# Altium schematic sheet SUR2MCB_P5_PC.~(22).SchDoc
size 420 x 297 mm; Scale: 1:1; Обозначение документа: АБВГ.123456.001 Э3
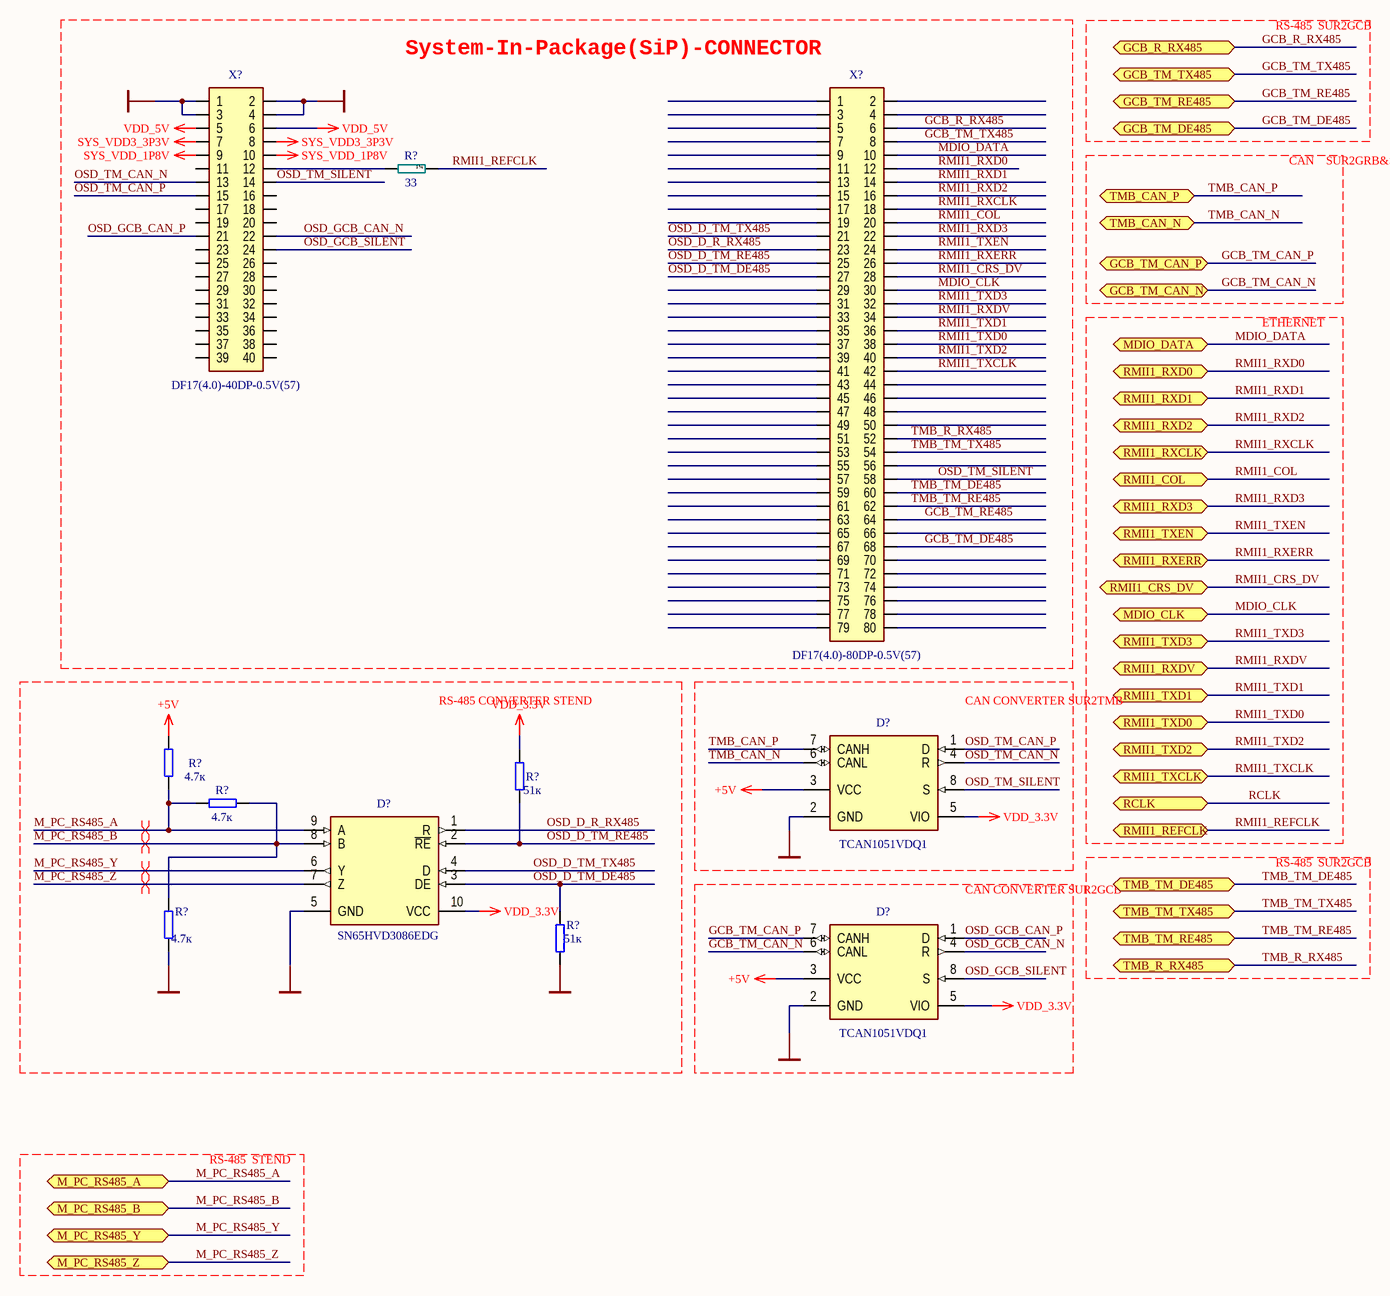
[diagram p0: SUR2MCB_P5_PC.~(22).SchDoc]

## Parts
(Parts that share a designator on the sheet are numbered #1, #2 ... from top to bottom, then left to right.)
D?#1  value TCAN1051VDQ1  [SOP-8-3.9X5-1.27]
D?#2  value SN65HVD3086EDG  [MSOP-10-3X3-0.5]
D?#3  value TCAN1051VDQ1  [SOP-8-3.9X5-1.27]
R?#1  value 33  [R0402]
R?#2  value 51к  [R0603]
R?#3  value 4.7к  [R0603]
R?#4  value 4.7к  [R0603]
R?#5  value 4.7к  [R0603]
R?#6  value 51к  [R0603]
X?#1  value DF17(4.0)-40DP-0.5V(57)  [DF17(4.0)-40DP-0.5V(57)]
X?#2  value DF17(4.0)-80DP-0.5V(57)  [DF17(4.0)-80DP-0.5V(57)]

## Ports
GCB_R_RX485 (bidir), GCB_TM_CAN_N (bidir), GCB_TM_CAN_P (bidir), GCB_TM_DE485 (bidir), GCB_TM_RE485 (bidir), GCB_TM_TX485 (bidir), M_PC_RS485_A (bidir), M_PC_RS485_B (bidir), M_PC_RS485_Y (bidir), M_PC_RS485_Z (bidir), MDIO_CLK (bidir), MDIO_DATA (bidir), RCLK (bidir), RMII1_COL (bidir), RMII1_CRS_DV (bidir), RMII1_REFCLK (bidir), RMII1_RXCLK (bidir), RMII1_RXD0 (bidir), RMII1_RXD1 (bidir), RMII1_RXD2 (bidir), RMII1_RXD3 (bidir), RMII1_RXDV (bidir), RMII1_RXERR (bidir), RMII1_TXCLK (bidir), RMII1_TXD0 (bidir), RMII1_TXD1 (bidir), RMII1_TXD2 (bidir), RMII1_TXD3 (bidir), RMII1_TXEN (bidir), TMB_CAN_N (bidir), TMB_CAN_P (bidir), TMB_R_RX485 (bidir), TMB_TM_DE485 (bidir), TMB_TM_RE485 (bidir), TMB_TM_TX485 (bidir)

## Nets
+5V: D?#1.3(VCC) D?#3.3(VCC) R?#3.1
GND: D?#1.2(GND) D?#2.5(GND) D?#3.2(GND) R?#5.2 R?#6.2 X?#1.1 X?#1.2 X?#1.3 X?#1.4
SYS_VDD3_3P3V: X?#1.7 X?#1.8
SYS_VDD_1P8V: X?#1.9 X?#1.10
VDD_3.3V: D?#1.5(VIO) D?#2.10(VCC) D?#3.5(VIO) R?#2.2
VDD_5V: X?#1.5 X?#1.6
GCB_R_RX485: X?#2.6 ; port GCB_R_RX485
GCB_TM_CAN_N: D?#3.6(CANL) ; port GCB_TM_CAN_N
GCB_TM_CAN_P: D?#3.7(CANH) ; port GCB_TM_CAN_P
GCB_TM_DE485: X?#2.68 ; port GCB_TM_DE485
GCB_TM_RE485: X?#2.64 ; port GCB_TM_RE485
GCB_TM_TX485: X?#2.8 ; port GCB_TM_TX485
M_PC_RS485_A: D?#2.9(A) R?#3.2 R?#4.2 ; port M_PC_RS485_A
M_PC_RS485_B: D?#2.8(B) R?#4.1 R?#5.1 ; port M_PC_RS485_B
M_PC_RS485_Y: D?#2.6(Y) ; port M_PC_RS485_Y
M_PC_RS485_Z: D?#2.7(Z) ; port M_PC_RS485_Z
MDIO_CLK: X?#2.30 ; port MDIO_CLK
MDIO_DATA: X?#2.10 ; port MDIO_DATA
OSD_D_R_RX485: D?#2.1(R) X?#2.23
OSD_D_TM_DE485: D?#2.3(DE) R?#6.1 X?#2.27
OSD_D_TM_RE485: D?#2.2(~{RE}) R?#2.1 X?#2.25
OSD_D_TM_TX485: D?#2.4(D) X?#2.21
OSD_GCB_CAN_N: D?#3.4(R) X?#1.22
OSD_GCB_CAN_P: D?#3.1(D) X?#1.21
OSD_GCB_SILENT: D?#3.8(S) X?#1.24
OSD_TM_CAN_N: D?#1.4(R) X?#1.13
OSD_TM_CAN_P: D?#1.1(D) X?#1.15
OSD_TM_SILENT: D?#1.8(S) X?#1.14 X?#2.58
RMII1_COL: X?#2.20 ; port RMII1_COL
RMII1_CRS_DV: X?#2.28 ; port RMII1_CRS_DV
RMII1_REFCLK: R?#1.2 ; port RMII1_REFCLK
RMII1_RXCLK: X?#2.18 ; port RMII1_RXCLK
RMII1_RXD0: X?#2.12 ; port RMII1_RXD0
RMII1_RXD1: X?#2.14 ; port RMII1_RXD1
RMII1_RXD2: X?#2.16 ; port RMII1_RXD2
RMII1_RXD3: X?#2.22 ; port RMII1_RXD3
RMII1_RXDV: X?#2.34 ; port RMII1_RXDV
RMII1_RXERR: X?#2.26 ; port RMII1_RXERR
RMII1_TXCLK: X?#2.42 ; port RMII1_TXCLK
RMII1_TXD0: X?#2.38 ; port RMII1_TXD0
RMII1_TXD1: X?#2.36 ; port RMII1_TXD1
RMII1_TXD2: X?#2.40 ; port RMII1_TXD2
RMII1_TXD3: X?#2.32 ; port RMII1_TXD3
RMII1_TXEN: X?#2.24 ; port RMII1_TXEN
TMB_CAN_N: D?#1.6(CANL) ; port TMB_CAN_N
TMB_CAN_P: D?#1.7(CANH) ; port TMB_CAN_P
TMB_R_RX485: X?#2.52 ; port TMB_R_RX485
TMB_TM_DE485: X?#2.60 ; port TMB_TM_DE485
TMB_TM_RE485: X?#2.62 ; port TMB_TM_RE485
TMB_TM_TX485: X?#2.54 ; port TMB_TM_TX485
NetR?#1_1: R?#1.1 X?#1.12

Not connected (* = marked no-connect by the designer): X?#1 11 16 17 18 19 20 23 25 26 27 28 29 30 31 32 33 34 35 36 37 38 39 40; X?#2 1 2 3 4 5 7 9 11 13 15 17 19 29 31 33 35 37 39 41 43 44 45 46 47 48 49 50 51 53 55 56 57 59 61 63 65 66 67 69 70 71 72 73 74 75 76 77 78 79 80

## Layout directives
differential pair: M_PC_RS485_A, M_PC_RS485_B, M_PC_RS485_Y, M_PC_RS485_Z

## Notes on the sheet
- System-In-Package(SiP)-CONNECTOR
- RS-485  SUR2GCB
- CAN    SUR2GRB&SUR2GCB
- ETHERNET
- RS-485 CONVERTER STEND
- (near D?#1) CAN CONVERTER SUR2TMB
- (near D?#3) CAN CONVERTER SUR2GCB
- RS-485  STEND

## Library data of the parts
D?#1 D?#3 = TCAN1051VDQ1: CAN Transceiver 8-SOIC 5V; ValueManufacturer: Texas Instruments; PowerVoltage: 4.5V~5.5V; ValueDescription: TCAN1051VDQ1  CAN приемопередатчик 4.5V~5.5V  8-SOIC (3.90mm)
D?#2 = SN65HVD3086EDG: RS422 RS485 FULL Transceiver 8-SOIC 5V; ValueManufacturer: Texas Instruments; PowerVoltage: 4.5V~5.5V; ValueDescription: SN65HVD3086EDG  FULL RS485/RS422 приемопередатчик 4.5V~5.5V  10-SOP (3.00mm)
R?#1 = R-0402-1%: SMD 0402 0.1Вт ±1% 50В; ValueManufacturer: Panasonic; ValueManufacturerPartNumber: ERJ-2RK; PowerVoltage: 0.1Вт 50В; ValueDescription: 0402 (1005)  0.1Вт 50В  33Ом ±1%; ValueType: Chip Resistor
R?#2 R?#6 = R-0603-5%: SMD 0603 0.1Вт ±5% 75В; ValueManufacturer: Panasonic; ValueManufacturerPartNumber: ERJ-3GE; PowerVoltage: 0.1Вт 75В; ValueDescription: 0603 (1608)  0.1Вт 75В  51кОм ±5%; ValueType: Chip Resistor
R?#3-R?#5 = R-0603-5%: SMD 0603 0.1Вт ±5% 75В; ValueManufacturer: Panasonic; ValueManufacturerPartNumber: ERJ-3GE; PowerVoltage: 0.1Вт 75В; ValueDescription: 0603 (1608)  0.1Вт 75В  4.7кОм ±5%; ValueType: Chip Resistor
X?#1 = DF17(4.0)-40DP-0.5V(57): CONN HEADER 40POS .5MM SMD W/FIT; ValueManufacturer: Hirose Electric Co Ltd; PowerVoltage: 50V; TechSpec: Шаг 0.5; ValueDescription: DF17(4.0)-40DP-0.5V(57) Двухрядная вилка Hirose Electric Co Ltd  15.2x4.7mm  Шаг 0.5; ValueType: Connector
X?#2 = DF17(4.0)-80DP-0.5V(57): CONN HEADER 80POS .5MM SMD W/FIT; ValueManufacturer: Hirose Electric Co Ltd; PowerVoltage: 50V; TechSpec: Шаг 0.5; ValueDescription: DF17(4.0)-80DP-0.5V(57) Двухрядная вилка Hirose Electric Co Ltd  25.2x4.7mm  Шаг 0.5; ValueType: Connector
